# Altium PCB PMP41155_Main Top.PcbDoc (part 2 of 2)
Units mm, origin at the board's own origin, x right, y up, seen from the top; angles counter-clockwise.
Board outline 74 x 151.7 mm, 8 copper layers (Top Layer, Signal Layer 1, Signal Layer 2, Signal Layer 3, Signal Layer 4, Signal Layer 5, Signal Layer 6, Bottom Layer), stack 1.534 mm thick; 14 components, 3 nets, 47 pads, 370 vias.
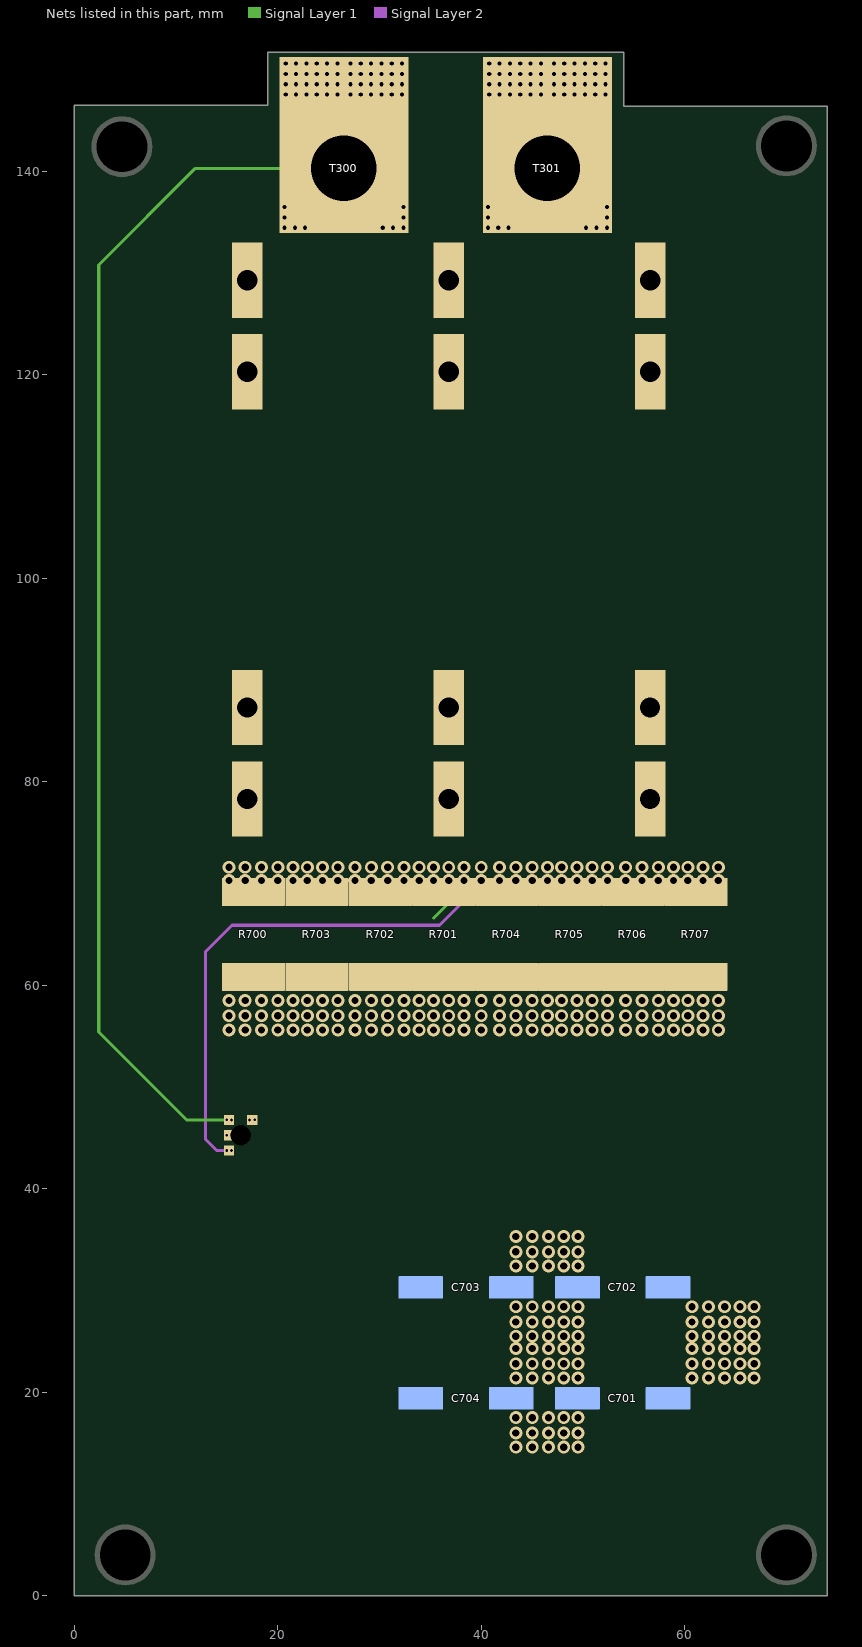
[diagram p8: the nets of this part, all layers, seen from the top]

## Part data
C701 C702 C703 C704: library part CMP-0040749-1, "100 µF 63 V Aluminum - Polymer Capacitors Radial, Can - SMD 2000 Hrs @ 125°C", Digikey Part Number=399-A769MS107M1JLAS018CT-ND, Leakage Current=1260uA, Manufacturer=KEMET, Mouser Part Number=80-A769MS107M1JLAS18, Operating Temperature Range="-55°C to +125°C", Tolerance_%=20%, ValueDisplayed=100uF
R700 R701 R702 R703 R704 R705 R706 R707: library part CMP-0096319-1, "400 µOhms ±1% 9W Chip Resistor Nonstandard Automotive AEC-Q200, Current Sense, Moisture Resistant Metal Element", Digikey Part Number=YAG6132CT-ND, Manufacturer=YAGEO, Mouser Part Number=603-PU3921FKNP90U4L, Operating Temperature Range="-65°C to +170°C", Power_W=9W, TempCo=175ppm/°C, Tolerance_%=1%
T300 T301: library part CMP-0055443-2, "Terminal 90A Lug", Manufacturer=Panduit, Supplier Part Number 1=CB70-14-CY-ND, Voltage_V=600V

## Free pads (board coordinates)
  round 6 hole 5: 1(4.68,142.42) 1(5,4) 1(70,4) 1(70,142.5)
  rect 1x1 hole 0.3 copper offset -0.254,0: 1(15.46,45.26) 1(15.46,46.76) 1(15.46,43.76)
  rect 1x1 hole 0.3 copper offset 0.254,0: 1(17.24,46.76)
  rect 0.8x1.6 hole 2 square unplated: 2(16.35,45.26)
  rect 3x7.4 hole 2 square unplated: 2(16.99,78.307) 2(16.99,87.307) 2(17,120.3) 2(17,129.3) 2(36.79,78.307) 2(36.79,87.307) 2(36.8,120.3) 2(36.8,129.3) 2(56.59,78.307) 2(56.59,87.307) 2(56.6,120.3) 2(56.6,129.3)

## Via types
v1: diameter 1.27, hole 0.711, Top Layer to Bottom Layer, 250 vias
v2: diameter 0.813, hole 0.406, Top Layer to Bottom Layer, 116 vias
v3: diameter 0.508, hole 0.254, Top Layer to Bottom Layer, tented both sides, 4 vias

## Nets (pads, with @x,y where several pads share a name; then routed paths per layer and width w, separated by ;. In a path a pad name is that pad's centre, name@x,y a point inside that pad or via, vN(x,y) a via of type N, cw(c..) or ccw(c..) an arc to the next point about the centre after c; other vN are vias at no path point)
CS+_total_charge_current_battery: C701.2 C702.2 pad.1@15.46,43.76 pad.2@16.99,78.307 pad.2@17,120.3 pad.2@36.8,120.3 pad.2@36.79,78.307 pad.2@56.6,120.3 pad.2@56.59,78.307 R700.2 R701.2 R702.2 R703.2 R704.2 R705.2 R706.2 R707.2 | length 55.5
  Signal Layer 2 w0.3: v3(14.98,43.76) 14,43.76 12.9,44.86 12.9,63.3 15.5,65.9 35.9,65.9 38.3,68.3 v1(38.3,70.3)
  Signal Layer 1 w0.3: 35.3,66.6 38.183,69.483 38.183,70.3 v1(38.3,70.3)
  other v1: 60.716,21.4 62.326,21.4 63.926,21.4 65.426,21.4 66.826,21.4 60.716,22.8 62.326,22.8 63.926,22.8 65.426,22.8 66.826,22.8 60.716,24.3 62.326,24.3 63.926,24.3 65.426,24.3 66.826,24.3 60.716,25.5 62.326,25.5 63.926,25.5 65.426,25.5 66.826,25.5 60.716,26.9 62.326,26.9 63.926,26.9 65.426,26.9 66.826,26.9 60.716,28.4 62.326,28.4 63.926,28.4 65.426,28.4 66.826,28.4 15.2,70.3 16.79,70.3 18.4,70.3 20,70.3 21.5,70.3 22.9,70.3 24.4,70.3 25.9,70.3 27.6,70.3 29.19,70.3 30.8,70.3 32.4,70.3 33.9,70.3 35.3,70.3 36.8,70.3 40,70.3 41.79,70.3 43.4,70.3 45,70.3 46.5,70.3 47.9,70.3 49.4,70.3 50.9,70.3 52.4,70.3 54.19,70.3 55.8,70.3 57.4,70.3 58.9,70.3 60.3,70.3 61.8,70.3 63.3,70.3 15.2,71.6 16.79,71.6 18.4,71.6 20,71.6 21.5,71.6 22.9,71.6 24.4,71.6 25.9,71.6 27.6,71.6 29.19,71.6 30.8,71.6 32.4,71.6 33.9,71.6 35.3,71.6 36.8,71.6 38.3,71.6 40,71.6 41.79,71.6 43.4,71.6 45,71.6 46.5,71.6 47.9,71.6 49.4,71.6 50.9,71.6 52.4,71.6 54.19,71.6 55.8,71.6 57.4,71.6 58.9,71.6 60.3,71.6 61.8,71.6 63.3,71.6
CS-_total_charge_current_battery: C703.2 C704.2 pad.1@15.46,45.26 pad.1@15.46,46.76 R700.1 R701.1 R702.1 R703.1 R704.1 R705.1 R706.1 R707.1 T300.1 | length 119.3
  Signal Layer 1 w0.3: 14.69,46.76 11.04,46.76 2.4,55.4 2.4,130.8 11.9,140.3 T300.1@26.5,140.3
  other v1: 15.2,55.6 16.79,55.6 18.4,55.6 20,55.6 21.5,55.6 22.9,55.6 24.4,55.6 25.9,55.6 27.6,55.6 29.19,55.6 30.8,55.6 32.4,55.6 33.9,55.6 35.3,55.6 36.8,55.6 38.3,55.6 40,55.6 41.79,55.6 43.4,55.6 45,55.6 46.5,55.6 47.9,55.6 49.4,55.6 50.9,55.6 52.4,55.6 54.19,55.6 55.8,55.6 57.4,55.6 58.9,55.6 60.3,55.6 61.8,55.6 63.3,55.6 15.2,57 16.79,57 18.4,57 20,57 21.5,57 22.9,57 24.4,57 25.9,57 27.6,57 29.19,57 30.8,57 32.4,57 33.9,57 35.3,57 36.8,57 38.3,57 40,57 41.79,57 43.4,57 45,57 46.5,57 47.9,57 49.4,57 50.9,57 52.4,57 54.19,57 55.8,57 57.4,57 58.9,57 60.3,57 61.8,57 63.3,57 15.2,58.5 16.79,58.5 18.4,58.5 20,58.5 21.5,58.5 22.9,58.5 24.4,58.5 25.9,58.5 27.6,58.5 29.19,58.5 30.8,58.5 32.4,58.5 33.9,58.5 35.3,58.5 36.8,58.5 38.3,58.5 40,58.5 41.79,58.5 43.4,58.5 45,58.5 46.5,58.5 47.9,58.5 49.4,58.5 50.9,58.5 52.4,58.5 54.19,58.5 55.8,58.5 57.4,58.5 58.9,58.5 60.3,58.5 61.8,58.5 63.3,58.5
  other v2: 20.658,134.458 21.674,134.458 22.69,134.458 30.31,134.458 31.326,134.458 32.342,134.458 20.658,135.474 32.342,135.474 20.658,136.49 32.342,136.49 20.785,147.539 21.801,147.539 22.817,147.539 23.833,147.539 24.849,147.539 25.865,147.539 27.135,147.539 28.151,147.539 29.167,147.539 30.183,147.539 31.199,147.539 32.215,147.539 20.785,148.555 21.801,148.555 22.817,148.555 23.833,148.555 24.849,148.555 25.865,148.555 27.135,148.555 28.151,148.555 29.167,148.555 30.183,148.555 31.199,148.555 32.215,148.555 20.785,149.571 21.801,149.571 22.817,149.571 23.833,149.571 24.849,149.571 25.865,149.571 27.135,149.571 28.151,149.571 29.167,149.571 30.183,149.571 31.199,149.571 32.215,149.571 20.785,150.587 21.801,150.587 22.817,150.587 23.833,150.587 24.849,150.587 25.865,150.587 27.135,150.587 28.151,150.587 29.167,150.587 30.183,150.587 31.199,150.587 32.215,150.587
  other v3: 14.98,45.26 14.98,46.76
VBAT-: C701.1 C702.1 C703.1 C704.1 pad.1@17.24,46.76 pad.2@16.99,87.307 pad.2@17,129.3 pad.2@36.8,129.3 pad.2@36.79,87.307 pad.2@56.6,129.3 pad.2@56.59,87.307 T301.1
  other v1: 43.4,14.6 45.01,14.6 46.61,14.6 48.11,14.6 49.51,14.6 43.4,16 45.01,16 46.61,16 48.11,16 49.51,16 43.4,17.5 45.01,17.5 46.61,17.5 48.11,17.5 49.51,17.5 43.4,21.4 45.01,21.4 46.61,21.4 48.11,21.4 49.51,21.4 43.4,22.8 45.01,22.8 46.61,22.8 48.11,22.8 49.51,22.8 43.4,24.3 45.01,24.3 46.61,24.3 48.11,24.3 49.51,24.3 43.4,25.5 45.01,25.5 46.61,25.5 48.11,25.5 49.51,25.5 43.4,26.9 45.01,26.9 46.61,26.9 48.11,26.9 49.51,26.9 43.4,28.4 45.01,28.4 46.61,28.4 48.11,28.4 49.51,28.4 43.4,32.4 45.01,32.4 46.61,32.4 48.11,32.4 49.51,32.4 43.4,33.8 45.01,33.8 46.61,33.8 48.11,33.8 49.51,33.8 43.4,35.3 45.01,35.3 46.61,35.3 48.11,35.3 49.51,35.3
  other v2: 40.658,134.458 41.674,134.458 42.69,134.458 50.31,134.458 51.326,134.458 52.342,134.458 40.658,135.474 52.342,135.474 40.658,136.49 52.342,136.49 40.785,147.539 41.801,147.539 42.817,147.539 43.833,147.539 44.849,147.539 45.865,147.539 47.135,147.539 48.151,147.539 49.167,147.539 50.183,147.539 51.199,147.539 52.215,147.539 40.785,148.555 41.801,148.555 42.817,148.555 43.833,148.555 44.849,148.555 45.865,148.555 47.135,148.555 48.151,148.555 49.167,148.555 50.183,148.555 51.199,148.555 52.215,148.555 40.785,149.571 41.801,149.571 42.817,149.571 43.833,149.571 44.849,149.571 45.865,149.571 47.135,149.571 48.151,149.571 49.167,149.571 50.183,149.571 51.199,149.571 52.215,149.571 40.785,150.587 41.801,150.587 42.817,150.587 43.833,150.587 44.849,150.587 45.865,150.587 47.135,150.587 48.151,150.587 49.167,150.587 50.183,150.587 51.199,150.587 52.215,150.587
  other v3: 17.72,46.76

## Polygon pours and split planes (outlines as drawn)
CS+_total_charge_current_battery on Top Layer "TOP_LAYER_CS+_TOTAL_CHARGE_CURRENT_BATTERY_P007" (solid, pour order 7): 62.4,125.1 69.1,118.4 69.1,70.4 65.4,66.7 7.3,66.7 4.1,69.9 4.1,117.7 11.5,125.1
CS-_total_charge_current_battery on Top Layer "TOP_LAYER_CS-_TOTAL_CHARGE_CURRENT_BATTERY_P005" (solid, pour order 5): 14.309,62.8 63.936,62.8 64.8,61.936 64.8,55.132 63.968,54.3 14.2,54.3 13.5,55 13.5,62.222
VBAT- on Top Layer "TOP_LAYER_VBAT-_P003" (solid, pour order 3): 1,146 73,146 73,1 1,1
VBAT- on Signal Layer 5 "SIGNAL_LAYER_5_VBAT-_P001" (solid, pour order 1): 1,146 73,146 73,1 1,1
CS-_total_charge_current_battery on Top Solder "TOP_LAYER_CS-_TOTAL_CHARGE_CURRENT_BATTERY_P000" (solid, pour order 0): 14.309,62.8 63.936,62.8 64.8,61.936 64.8,55.132 63.968,54.3 14.2,54.3 13.5,55 13.5,62.222
no net on Top Solder "TOP_LAYER_CS+_TOTAL_CHARGE_CURRENT_BATTERY_P002" (solid): 62.514,82.191 69.1,75.605 69.1,70.6 65.3,66.8 7.2,66.8 4.214,69.786 4.214,75.314 11.091,82.191
CS+_total_charge_current_battery on Top Solder "TOP_LAYER_CS+_TOTAL_CHARGE_CURRENT_BATTERY_P002" (solid, pour order 2): 62.4,125.1 69.1,118.4 69.1,97.4 63.4,91.7 8.7,91.7 4.1,96.3 4.1,117.7 11.5,125.1
CS-_total_charge_current_battery on Signal Layer 4 "SIGNAL_LAYER_4_CS-_TOTAL_CHARGE_CURRENT_BATTERY_P011" (solid, pour order 11): 1,146 73,146 73,1 1,1
CS+_total_charge_current_battery on Bottom Layer "BOTTOM_LAYER_CS+_TOTAL_CHARGE_CURRENT_BATTERY_P010" (solid, pour order 10): 62.4,125.1 69.1,118.4 69.1,70.4 65.4,66.7 7.3,66.7 4.1,69.9 4.1,117.7 11.5,125.1
CS+_total_charge_current_battery on Bottom Layer "BOTTOM_LAYER_CS+_TOTAL_CHARGE_CURRENT_BATTERY_P004" (solid, pour order 4): 52.3,34.6 53.939,36.239 66.261,36.239 68,34.5 68,14.2 66.4,12.6 53.7,12.6 52.3,14
CS-_total_charge_current_battery on Bottom Layer "BOTTOM_LAYER_CS-_TOTAL_CHARGE_CURRENT_BATTERY_P009" (solid, pour order 9): 5.7,63.5 67.7,63.5 72.8,58.4 72.8,2.3 71.6,1.1 2.3,1.1 1.1,2.3 1.1,58.9
VBAT- on Bottom Layer "BOTTOM_LAYER_VBAT-_P006" (solid, pour order 6): 40.8,34 42.8,36 50.2,36 51.716,34.484 51.716,14.516 49.8,12.6 42.6,12.6 40.7,14.5 40.7,33.8
CS-_total_charge_current_battery on Signal Layer 3 "SIGNAL_LAYER_3_CS-_TOTAL_CHARGE_CURRENT_BATTERY_P012" (solid, pour order 12): 1,146 73,146 73,1 1,1
CS+_total_charge_current_battery on Signal Layer 1 "SIGNAL_LAYER_1_CS+_TOTAL_CHARGE_CURRENT_BATTERY_P008" (solid, pour order 8): 62.4,125.1 69.1,118.4 69.1,19.9 62.2,13 25.2,13 4.1,34.1 4.1,117.7 11.5,125.1
VBAT- on Signal Layer 2 "SIGNAL_LAYER_2_VBAT-_P014" (solid, pour order 14): 1,146 73,146 73,1 1,1
CS-_total_charge_current_battery on Signal Layer 6 "SIGNAL_LAYER_6_CS-_TOTAL_CHARGE_CURRENT_BATTERY_P016" (solid, pour order 16): 1,146 73,146 73,1 1,1
no net on Bottom Solder "NONET_L-01_P-001" (solid): 12.5,124.2 61.2,124.2 67.4,118 67.4,94.9 67.3,94.9 64.8,92.4 12.4,92.4 6.2,98.6 6.2,117.8 12.7,124.3
no net on Bottom Solder "NONET_L-01_P-001" (solid): 14.009,60.27 63.609,60.27 65.609,58.27 65.609,38.2 28.478,38.2 11.409,55.27 11.409,57.67
CS+_total_charge_current_battery on Bottom Solder "NONET_L-01_P-001" (solid): 13,73.6 62.6,73.6 64.6,71.6 64.6,67.9 63.3,66.6 12.4,66.6 10.4,68.6 10.4,71

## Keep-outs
Keep-Out Layer:
  text ".Layer_Name" at 1.274,-44.839 h1.52

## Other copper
Top Layer:
  text ".Layer_Name" at 1.274,-44.839 h1.52
Bottom Layer:
  text ".Layer_Name" at 1.274,-44.839 h1.52

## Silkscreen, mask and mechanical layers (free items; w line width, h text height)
Top Overlay:
  text ".Layer_Name" at 1.274,-44.839 h1.52
Bottom Overlay:
  text ".Layer_Name" at 1.274,-44.839 h1.52
Top Paste:
  text ".Layer_Name" at 1.274,-44.839 h1.52
Bottom Paste:
  text ".Layer_Name" at 1.274,-44.839 h1.52
Top Solder:
  pour cut-out: 15.5,91 18.5,91 18.5,83.6 15.5,83.6
  text ".Layer_Name" at 1.274,-44.839 h1.52
  text ".Layer_Name" at 1.274,-44.839 h1.52
Bottom Solder:
  text ".Layer_Name" at 1.274,-44.839 h1.52
Drill Guide:
  text ".Layer_Name" at 1.274,-44.839 h1.52
M1 Board Outline:
  lines w0.178: 0,0 0,145 74,145 74,0 0,0
  lines w0.254: 74,0 74,146.4 54,146.4 54,151.7 19,151.7 19,146.5 0,146.5 0,0 74,0 ; 74,0 74,0
  text ".Layer_Name" at 1.274,-44.839 h1.52
M2 Board Dimensions:
  rectangle: -13.382,-30.018 -10.207,-26.843
  rectangle: -10.207,-33.193 -0.682,-30.018
  lines w0.178: -13.382,-30.018 12.018,-30.018 ; -10.207,-33.193 -10.207,-26.843 ; -7.032,-33.193 -7.032,-26.843 ; -0.682,-33.193 -0.682,-26.843 ; 5.668,-33.193 5.668,-26.843 ; -13.382,-33.193 -13.382,-26.843 12.018,-26.843 12.018,-33.193 -13.382,-33.193
  text ".Layer_Name" at 1.274,-44.839 h1.52
M3 3D STEP Top:
  text ".Layer_Name" at 1.274,-44.839 h1.52
M4 3D STEP Bottom:
  text ".Layer_Name" at 1.274,-44.839 h1.52
M5 Assembly Top:
  lines w0.254: -20.799,-46.659 146.841,-46.659 ; -20.799,-41.495 146.892,-41.495 ; -20.799,-36.33 -20.799,-51.824 80.928,-51.824 146.892,-51.824 146.892,-36.33 -20.786,-36.33 -20.786,-51.824 19.232,-51.824 ; 41.812,-51.824 41.812,-36.33 ; 73.994,-41.495 73.994,-36.33 ; 95.33,-41.495 95.33,-36.33 ; 111.129,-51.989 111.129,-46.837
  text "COMPONENTS MARKED 'DNP' SHOULD NOT BE POPULATED." at 15.917,-31.123 h1.52
  text "ASSEMBLY VARIANT:" at 15.904,-34.057 h1.52
  text ".VariantName" at 42.219,-34.057 h1.52
  text "PCB VIEWED FROM TOP SIDE" at -19.186,-39.687 h1.52
  text "BOARD #:" at 43.717,-39.687 h1.52
  text ".PRJ_Number" at 57.573,-39.687 h1.52
  text "REV:" at 79.023,-39.687 h1.52
  text ".PCB_Rev" at 86.427,-39.687 h1.52
  text "SVN REV:" at 100.308,-39.687 h1.52
  text ".VersionControl_RevNumber" at 113.161,-39.687 h1.52
  text "TID #:" at 43.717,-44.852 h1.52
  text ".TID" at 57.573,-44.852 h1.52
  text "PLOT NAME =" at -19.186,-50.067 h1.52
  text ".plot_File_Name" at 1.274,-50.067 h1.52
  text "GENERATED    :" at 43.768,-50.067 h1.52
  text ".Print_Date" at 65.853,-50.067 h1.52
  text ".Print_Time" at 84.37,-50.067 h1.52
  text "TEXAS INSTRUMENTS" at 116.488,-50.067 h1.52
M6 Assembly Bottom:
  lines w0.254: -20.811,-41.507 146.879,-41.507 ; -20.761,-46.672 146.879,-46.672 ; 14.952,-52.002 14.952,-46.85 ; 30.751,-41.507 30.751,-36.343 ; 52.087,-41.507 52.087,-36.343 ; 84.268,-51.837 84.268,-36.343 ; 106.849,-51.837 146.867,-51.837 146.867,-36.343 -20.811,-36.343 -20.811,-51.837 45.152,-51.837 146.879,-51.837 146.879,-36.343
  text "COMPONENTS MARKED 'DNP' SHOULD NOT BE POPULATED." at 141.609,-31.11 h1.52
  text ".VariantName" at 115.091,-34.057 h1.52
  text "ASSEMBLY VARIANT:" at 141.482,-34.057 h1.52
  text ".VersionControl_RevNumber" at 12.92,-39.7 h1.52
  text "SVN REV:" at 25.772,-39.7 h1.52
  text ".PCB_Rev" at 39.653,-39.7 h1.52
  text "REV:" at 47.057,-39.7 h1.52
  text ".PRJ_Number" at 68.508,-39.7 h1.52
  text "BOARD #:" at 82.363,-39.7 h1.52
  text "PCB VIEWED FROM BOTTOM SIDE" at 145.266,-39.7 h1.52
  text ".TID" at 68.508,-44.864 h1.52
  text "TID #:" at 82.363,-44.864 h1.52
  text "TEXAS INSTRUMENTS" at 9.592,-50.08 h1.52
  text ".Print_Time" at 41.711,-50.08 h1.52
  text ".Print_Date" at 60.227,-50.08 h1.52
  text "GENERATED    :" at 82.313,-50.08 h1.52
  text ".plot_File_Name" at 124.807,-50.08 h1.52
  text "PLOT NAME =" at 145.266,-50.08 h1.52
M9 Title Sheet:
  drawing of 57 lines, arcs and shapes, not listed
  text "2" at 63.83,181.099 h1.78
  text "1" at 5.41,181.094 h1.78
  text "3" at 132.029,181.094 h1.78
  text "4" at 195.698,181.094 h1.78
  text "5" at 259.173,181.094 h1.78
  text "6" at 322.8,181.094 h1.78
  text "A" at -23.961,152.062 h1.78
  text "A" at 351.959,152.062 h1.78
  text "B" at -23.961,91.61 h1.78
  text "B" at 351.959,91.61 h1.78
  text "C" at -23.961,31.285 h1.78
  text "C" at 351.959,31.285 h1.78
  text "PROJECT TITLE:" at 274.743,-15.985 h1.14
  text ".PRJ_Title" at 276.013,-19.371 h1.78
  text "DESIGNED FOR:" at 274.743,-23.63 h1.14
  text ".PRJ_Customer" at 276.013,-27.186 h1.78
  text "D" at -23.961,-28.913 h1.78
  text "D" at 351.959,-28.913 h1.78
  text "FILE NAME:" at 274.743,-31.25 h1.14
  text ".PCB_File_Name_No_Path" at 276.013,-34.298 h1.78
  text "Texas Instruments (TI) and/or its licensors do not warrant the accuracy or completeness of this specification" at 148.518,-38.409 h1.14
  text "ENGINEER:" at 274.743,-38.616 h1.14
  text "LAYOUT BY:" at 312.97,-38.616 h1.14
  text "or any information contained therein. TI and/or its licensors do not warrant that this design will meet" at 147.375,-41.27 h1.14
  text ".PRJ_Engineer" at 276.013,-42.553 h1.78
  text ".PCB_Layout" at 314.253,-42.553 h1.78
  text "the specifications, will be suitable for your application or fit for any particular purpose, or will operate in" at 147.375,-44.132 h1.14
  text ".Layer_Name" at 1.274,-44.839 h1.52
  text "ALTIUM DESIGNER VERSION:" at 312.97,-46.49 h1.14
  text "an implementation. TI and/or its licensors do not warrant that the design is production worthy. You should" at 147.375,-46.994 h1.14
  text "completely validate and test your design implementation to confirm the system functionality for your application." at 148.518,-49.855 h1.14
  text ".print_Scale" at 276.013,-49.876 h1.78
  text ".Application_BuildNumber" at 314.253,-49.876 h1.78
  text "1" at 5.41,-55.126 h1.78
  text "2" at 68.8,-55.126 h1.78
  text "3" at 132.029,-55.126 h1.78
  text "4" at 195.698,-55.126 h1.78
  text "5" at 259.173,-55.126 h1.78
  text "6" at 322.8,-55.126 h1.78
M10 Fab Notes:
  drawing of 189 lines, arcs and shapes, not listed
  text "DESIGN INFORMATION" at 301.121,138.414 h1.52
  text "MIN. TRACK WIDTH:" at 284.749,135.058 h1.52
  text "8" at 312.594,135.058 h1.52
  text "MIL" at 316.525,135.058 h1.52
  text "MIN. CLEARANCE:" at 284.749,131.905 h1.52
  text "0.2" at 311.07,131.905 h1.52
  text "mm" at 316.525,131.905 h1.52
  text "MIN. VIA PAD SIZE:" at 284.749,128.752 h1.52
  text "24" at 311.832,128.752 h1.52
  text "MIL" at 316.525,128.752 h1.52
  text "0.05mm (2MIL)" at 302.402,125.453 h1.52
  text "MINIMUM ANNULAR RING" at 276.387,125.244 h1.52
  text "EXTERNAL" at 320.386,125.244 h1.52
  text "PER" at 281.467,122.447 h1.52
  text "IPC-D-275 CLASS 2 LEVEL C" at 287.055,122.447 h1.52
  text "MIL, HOLES" at 324.856,119.894 h1.52
  text "+/-" at 314.888,119.676 h1.52
  text "+/-" at 336.579,119.676 h1.52
  text "REGISTRATION TOLERANCES:" at 276.387,119.649 h1.52
  text "METAL" at 306.861,119.649 h1.52
  text "5" at 321.497,119.649 h1.52
  text "3" at 342.655,119.649 h1.52
  text "MIL" at 345.608,119.649 h1.52
  text "HOLE SIZE TOLERANCE (UNLESS OTHERWISE SPECIFIED):" at 276.387,117.152 h1.52
  text "+/-" at 336.579,117.079 h1.52
  text "3" at 342.655,117.052 h1.52
  text "MIL" at 345.608,117.052 h1.52
  text "MATERIAL:" at 274.488,113.556 h1.52
  text "FR-4 High Tg" at 299.544,110.291 h1.52
  text "X" at 295.875,110.088 h1.52
  text "FR-408" at 285.181,109.974 h1.52
  text "OTHER" at 322.976,109.974 h1.52
  text "62 MIL (1.6mm) +/-10%" at 293.312,106.341 h1.52
  text "X" at 290.261,106.278 h1.52
  text "THICKNESS:" at 276.387,106.132 h1.52
  text "OTHER" at 325.948,106.132 h1.52
  text "TOLERANCE:" at 276.387,102.619 h1.52
  text "X" at 297.932,102.619 h1.52
  text "ANSI IPC-6012 TYPE 3 CLASS 2" at 302.454,102.619 h1.52
  text "OTHER +/-" at 302.453,98.956 h1.52
  text "BOW & TWIST:" at 276.387,95.269 h1.52
  text "X" at 297.932,95.269 h1.52
  text "ANSI IPC-6012 TYPE 3 CLASS 2" at 302.454,95.269 h1.52
  text "OTHER +/-" at 302.453,91.542 h1.52
  text "DRILLING:" at 274.488,88.225 h1.52
  text "NC_DRILL FILES" at 319.217,85.553 h1.52
  text "REFERENCE:" at 276.387,85.453 h1.52
  text "X" at 293.081,85.45 h1.52
  text "AS SHOWN" at 297.602,85.453 h1.52
  text "X" at 315.966,85.453 h1.52
  text "OTHER" at 326.786,81.84 h1.52
  text "PTH COPPER THICKNESS:" at 276.379,81.75 h1.52
  text "X" at 305.315,81.75 h1.52
  text "20-30 um" at 308.566,81.75 h1.52
  text "BOARD FINISH:" at 274.488,78.001 h1.52
  text "SILKSCREEN:" at 278.431,75.204 h1.52
  text "X" at 302.758,75.204 h1.52
  text "TOP" at 305.73,75.204 h1.52
  text "X" at 315.712,75.204 h1.52
  text "BOTTOM" at 318.709,75.204 h1.52
  text "SILKSCREEN COLOR:" at 278.431,71.262 h1.52
  text "X" at 302.733,71.262 h1.52
  text "WHITE" at 305.73,71.262 h1.52
  text "OTHER" at 318.709,71.262 h1.52
  text "X" at 306.06,67.619 h1.52
  text "GREEN" at 309.057,67.619 h1.52
  text "OTHER" at 324.754,67.619 h1.52
  text "SOLDER RESIST COLOR:" at 278.431,67.444 h1.52
  text "X" at 306.06,63.701 h1.52
  text "MATTE" at 309.057,63.701 h1.52
  text "SEMI-GLOSS" at 324.743,63.684 h1.52
  text "IMMERSION GOLD (ENIG)" at 301.437,59.312 h1.52
  text "ENEPIG" at 335.411,59.129 h1.52
  text "SURFACE FINISH:" at 274.488,59.103 h1.52
  text "X" at 296.916,59.103 h1.52
  text "IMM. TIN/SILVER OR EQUIV" at 282.858,55.616 h1.52
  text "OTHER" at 319.217,55.516 h1.52
  text "ARRAY/PANEL:" at 274.488,51.569 h1.52
  text "CUT AND TRIM PER M1 BOARD OUTLINE" at 301.437,51.36 h1.52
  text "N.C. ROUTE" at 301.437,47.907 h1.52
  text "X" at 318.913,47.907 h1.52
  text "V. SCORE" at 323.434,47.907 h1.52
  text "CERTIFICATION:" at 274.488,44.627 h1.52
  text "MATERIALS AND WORKMANSHIP FOR ALL PCBS" at 292.903,44.627 h1.52
  text "TO MEET OR EXCEED THE REQUIREMENTS OF:" at 292.903,42.238 h1.52
  text "X" at 283.696,38.97 h1.52
  text "ANSI IPC-A-600F CLASS ->" at 286.947,38.97 h1.52
  text "X" at 328.806,38.97 h1.52
  text "2" at 331.6,38.97 h1.52
  text "1" at 323.599,38.932 h1.52
  text "3" at 340.591,38.932 h1.52
  text "X" at 304.32,35.219 h1.52
  text "RoHS" at 307.571,35.219 h1.52
  text "OTHER" at 323.939,35.219 h1.52
  text "PER ORDER" at 334.025,35.219 h1.52
  text "ALL BOARDS MUST MEET OR EXCEED UL94-V0 REQUIREMENTS." at 275.187,31.312 h1.52
  text "PCB MUST BEAR THE UL94V-0 UL REGISTERED MATERIAL ID NUMBER" at 275.187,28.364 h1.52
  text "ADDITIONAL REQUIREMENTS:" at 274.488,24.061 h1.52
  text "MICROSECTION:" at 276.387,21.34 h1.52
  text "YES" at 299.393,21.34 h1.52
  text "REQUIRED" at 321.275,17.673 h1.52
  text "BARE BOARD ELEC. TEST:" at 276.387,17.601 h1.52
  text "NONE" at 309.553,17.601 h1.52
  text "X" at 318.278,17.601 h1.52
  text "PER ORDER" at 336.311,17.601 h1.52
  text "XX MIL VIAS REQUIRE NON-CONDUCTIVE FILL AND PLANARIZE" at 280.658,12.395 h1.5
  text "XX MIL VIAS REQUIRE CONDUCTIVE FILL AND PLANARIZE" at 280.861,9.754 h1.52
  text "OUTER XX MIL TRACES REQUIRE 50 OHM SINGLE-ENDED IMPEDANCE" at 280.836,5.604 h1.47
  text "LAYER 2 & 3 (INNER LAYERS) XX MIL WIDE, XX MIL SPACE / TRACES REQUIRE 100 OHM DIFFERENTIAL IMPEDANCE" at 280.633,-0.383 h1.52
  text ".Layer_Name" at 1.274,-44.839 h1.52
M11 Gerber Information:
  lines w0.254: -20.799,-46.659 146.841,-46.659 ; -20.799,-41.495 146.892,-41.495 ; -20.799,-36.33 -20.799,-51.824 80.928,-51.824 146.892,-51.824 146.892,-36.33 -20.786,-36.33 -20.786,-51.824 19.232,-51.824 ; 41.812,-51.824 41.812,-36.33 ; 73.994,-41.495 73.994,-36.33 ; 95.33,-41.495 95.33,-36.33 ; 111.129,-51.989 111.129,-46.837
  text "ALL ARTWORK VIEWED FROM TOP SIDE" at -19.186,-39.687 h1.52
  text "BOARD #:" at 43.717,-39.687 h1.52
  text ".PRJ_Number" at 57.573,-39.687 h1.52
  text "REV:" at 79.023,-39.687 h1.52
  text ".PCB_Rev" at 86.427,-39.687 h1.52
  text "SVN REV:" at 100.308,-39.687 h1.52
  text ".VersionControl_RevNumber" at 113.161,-39.687 h1.52
  text "LAYER NAME =" at -19.186,-44.839 h1.52
  text "TID #:" at 43.717,-44.852 h1.52
  text ".TID" at 57.573,-44.852 h1.52
  text "PLOT NAME =" at -19.186,-50.067 h1.52
  text ".plot_File_Name" at 1.274,-50.067 h1.52
  text "GENERATED    :" at 43.768,-50.067 h1.52
  text ".Print_Date" at 65.853,-50.067 h1.52
  text ".Print_Time" at 84.37,-50.067 h1.52
  text "TEXAS INSTRUMENTS" at 116.488,-50.067 h1.52
M12 Stackup:
  drawing of 503 lines, arcs and shapes, not listed
  text "Layer" at 140.899,156.092 h1.52
  text "Name" at 151.311,156.092 h1.52
  text "Material" at 175.18,156.092 h1.52
  text "Thickness" at 197.018,156.092 h1.52
  text "Constant" at 213.524,156.092 h1.52
  text "Board Layer Stack" at 227.998,156.092 h1.52
  text "Top Overlay" at 151.311,153.044 h1.52
  text "Top Solder" at 151.311,149.996 h1.52
  text "Solder Resist" at 175.18,149.996 h1.52
  text "0.39mil" at 197.018,149.996 h1.52
  text "3.5" at 213.524,149.996 h1.52
  text "1" at 140.899,146.948 h1.52
  text "Top Layer" at 151.311,146.948 h1.52
  text "2.80mil" at 197.018,146.948 h1.52
  text "Dielectric1" at 151.311,143.9 h1.52
  text "FR-4" at 175.18,143.9 h1.52
  text "5.00mil" at 197.018,143.9 h1.52
  text "4.2" at 213.524,143.9 h1.52
  text "2" at 140.899,140.852 h1.52
  text "Signal Layer 1" at 151.311,140.852 h1.52
  text "2.80mil" at 197.018,140.852 h1.52
  text "Dielectric 2" at 151.311,137.804 h1.52
  text "FR-4" at 175.18,137.804 h1.52
  text "6.00mil" at 197.018,137.804 h1.52
  text "4.2" at 213.524,137.804 h1.52
  text "3" at 140.899,134.756 h1.52
  text "Signal Layer 2" at 151.311,134.756 h1.52
  text "2.80mil" at 197.018,134.756 h1.52
  text "Dielectric 3" at 151.311,131.708 h1.52
  text "5.00mil" at 197.018,131.708 h1.52
  text "4.2" at 213.524,131.708 h1.52
  text "4" at 140.899,128.66 h1.52
  text "Signal Layer 3" at 151.311,128.66 h1.52
  text "2.80mil" at 197.018,128.66 h1.52
  text "Dielectric 4" at 151.311,125.612 h1.52
  text "6.00mil" at 197.018,125.612 h1.52
  text "4.2" at 213.524,125.612 h1.52
  text "5" at 140.899,122.564 h1.52
  text "Signal Layer 4" at 151.311,122.564 h1.52
  text "2.80mil" at 197.018,122.564 h1.52
  text "Dielectric 6" at 151.311,119.516 h1.52
  text "5.00mil" at 197.018,119.516 h1.52
  text "4.2" at 213.524,119.516 h1.52
  text "6" at 140.899,116.468 h1.52
  text "Signal Layer 5" at 151.311,116.468 h1.52
  text "2.80mil" at 197.018,116.468 h1.52
  text "Dielectric 7" at 151.311,113.42 h1.52
  text "6.00mil" at 197.018,113.42 h1.52
  text "4.2" at 213.524,113.42 h1.52
  text "7" at 140.899,110.372 h1.52
  text "Signal Layer 6" at 151.311,110.372 h1.52
  text "2.80mil" at 197.018,110.372 h1.52
  text "Dielectric 5" at 151.311,107.324 h1.52
  text "5.00mil" at 197.018,107.324 h1.52
  text "4.2" at 213.524,107.324 h1.52
  text "8" at 140.899,104.276 h1.52
  text "Bottom Layer" at 151.311,104.276 h1.52
  text "2.80mil" at 197.018,104.276 h1.52
  text "Bottom Solder" at 151.311,101.228 h1.52
  text "Solder Resist" at 175.18,101.228 h1.52
  text "0.39mil" at 197.018,101.228 h1.52
  text "3.5" at 213.524,101.228 h1.52
  text "Bottom Overlay" at 151.311,98.18 h1.52
  text ".Layer_Name" at 1.274,-44.839 h1.52
M13 Component Bodies Top:
  text ".Layer_Name" at 1.274,-44.839 h1.52
M14 Component Bodies Bottom:
  text ".Layer_Name" at 1.274,-44.839 h1.52
M15 Courtyards Top:
  text ".Layer_Name" at 1.274,-44.839 h1.52
M16 Courtyards Bottom:
  text ".Layer_Name" at 1.274,-44.839 h1.52
Drill Drawing:
  circle w0.254: c138.916,74.281 r0.421
  circle w0.254: c138.916,74.281 r0.702
  circle w0.254: c138.916,71.123 r0.702
  lines w0.254: 138.215,57.791 138.916,58.141 139.618,57.791 139.267,58.492 139.618,59.194 138.916,58.843 138.215,59.194 138.565,58.492 138.215,57.791 ; 138.215,60.948 139.618,60.948 139.618,62.352 138.215,62.352 138.215,60.948 ; 138.215,65.509 139.618,65.509 138.916,64.106 138.215,65.509 ; 138.215,67.615 138.565,67.615 138.916,67.264 139.267,67.615 139.618,67.615 139.267,67.965 139.618,68.316 139.267,68.316 138.916,68.667 138.565,68.316 138.215,68.316 138.565,67.965 138.215,67.615 ; 138.215,77.088 138.565,77.088 138.565,76.737 139.267,76.737 139.267,77.088 139.618,77.088 139.618,77.789 139.267,77.789 139.267,78.14 138.565,78.14 138.565,77.789 138.215,77.789 138.215,77.088 ; 138.215,79.895 138.215,80.245 138.565,80.596 138.215,80.947 138.215,81.298 138.565,81.298 138.916,80.947 139.267,81.298 139.618,81.298 139.618,80.947 139.267,80.596 139.618,80.245 139.618,79.895 139.267,79.895 138.916,80.245 138.565,79.895 138.215,79.895
  lines w0.305: 136.942,56.843 217.139,56.843 ; 136.942,82.105 217.139,82.105 ; 145.524,53.685 145.524,85.263 ; 153.186,53.685 153.186,85.263 ; 168.243,53.685 168.243,85.263 ; 174.825,53.685 174.825,85.263 ; 184.354,53.685 184.354,85.263 ; 202.752,53.685 202.752,85.263 ; 136.942,53.685 217.139,53.685 217.139,85.263 136.942,85.263 136.942,53.685
  text "Symbol" at 138.837,83.052 h1.83
  text "Count" at 146.471,83.052 h1.83
  text "Hole Size" at 154.133,83.052 h1.83
  text "Plated" at 169.19,83.052 h1.83
  text "Hole Type" at 175.772,83.052 h1.83
  text "Drill Layer Pair" at 185.301,83.052 h1.83
  text "Hole Tolerance" at 203.699,83.052 h1.83
  text "4" at 146.471,79.895 h1.52
  text "10.00mil (0.254mm)" at 154.133,79.895 h1.52
  text "PTH" at 169.19,79.895 h1.52
  text "Round" at 175.772,79.895 h1.52
  text "Top Layer - Bottom Layer" at 185.301,79.895 h1.52
  text "4" at 146.471,76.737 h1.52
  text "11.81mil (0.300mm)" at 154.133,76.737 h1.52
  text "PTH" at 169.19,76.737 h1.52
  text "Round" at 175.772,76.737 h1.52
  text "Top Layer - Bottom Layer" at 185.301,76.737 h1.52
  text "116" at 146.471,73.579 h1.52
  text "16.00mil (0.406mm)" at 154.133,73.579 h1.52
  text "PTH" at 169.19,73.579 h1.52
  text "Round" at 175.772,73.579 h1.52
  text "Top Layer - Bottom Layer" at 185.301,73.579 h1.52
  text "250" at 146.471,70.421 h1.52
  text "28.00mil (0.711mm)" at 154.133,70.421 h1.52
  text "PTH" at 169.19,70.421 h1.52
  text "Round" at 175.772,70.421 h1.52
  text "Top Layer - Bottom Layer" at 185.301,70.421 h1.52
  text "1" at 146.471,67.264 h1.52
  text "78.74mil (2.000mm)" at 154.133,67.264 h1.52
  text "NPTH" at 169.19,67.264 h1.52
  text "Rectangle" at 175.772,67.264 h1.52
  text "Top Layer - Bottom Layer" at 185.301,67.264 h1.52
  text "12" at 146.471,64.106 h1.52
  text "78.74mil (2.000mm)" at 154.133,64.106 h1.52
  text "NPTH" at 169.19,64.106 h1.52
  text "Rectangle" at 175.772,64.106 h1.52
  text "Top Layer - Bottom Layer" at 185.301,64.106 h1.52
  text "4" at 146.471,60.948 h1.52
  text "196.85mil (5.000mm)" at 154.133,60.948 h1.52
  text "PTH" at 169.19,60.948 h1.52
  text "Round" at 175.772,60.948 h1.52
  text "Top Layer - Bottom Layer" at 185.301,60.948 h1.52
  text "2" at 146.471,57.791 h1.52
  text "254.00mil (6.452mm)" at 154.133,57.791 h1.52
  text "PTH" at 169.19,57.791 h1.52
  text "Round" at 175.772,57.791 h1.52
  text "Top Layer - Bottom Layer" at 185.301,57.791 h1.52
  text "393 Total" at 146.471,54.633 h1.52
  text "Slot definitions :" at 138.837,52.422 h1.52
  text "Routed Path Length" at 150.285,52.422 h1.52
  text "= Calculated from tool start centre position to tool end centre position." at 163.994,52.422 h1.52
  text "Hole Length" at 150.285,51.159 h1.52
  text "= Routed Path Length + Tool Size = Slot length as defined in the PCB layout" at 158.92,51.159 h1.52
  text ".Layer_Name" at 1.274,-44.839 h1.52
M17 Embedded Cavity:
  text ".Layer_Name" at 1.274,-44.839 h1.52
M18 Embedded Assembly:
  text ".Layer_Name" at 1.274,-44.839 h1.52
M19 Embedded Keepout:
  text ".Layer_Name" at 1.274,-44.839 h1.52

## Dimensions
-13.382,-33.193 to 12.018,-33.193 on M2 Board Dimensions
